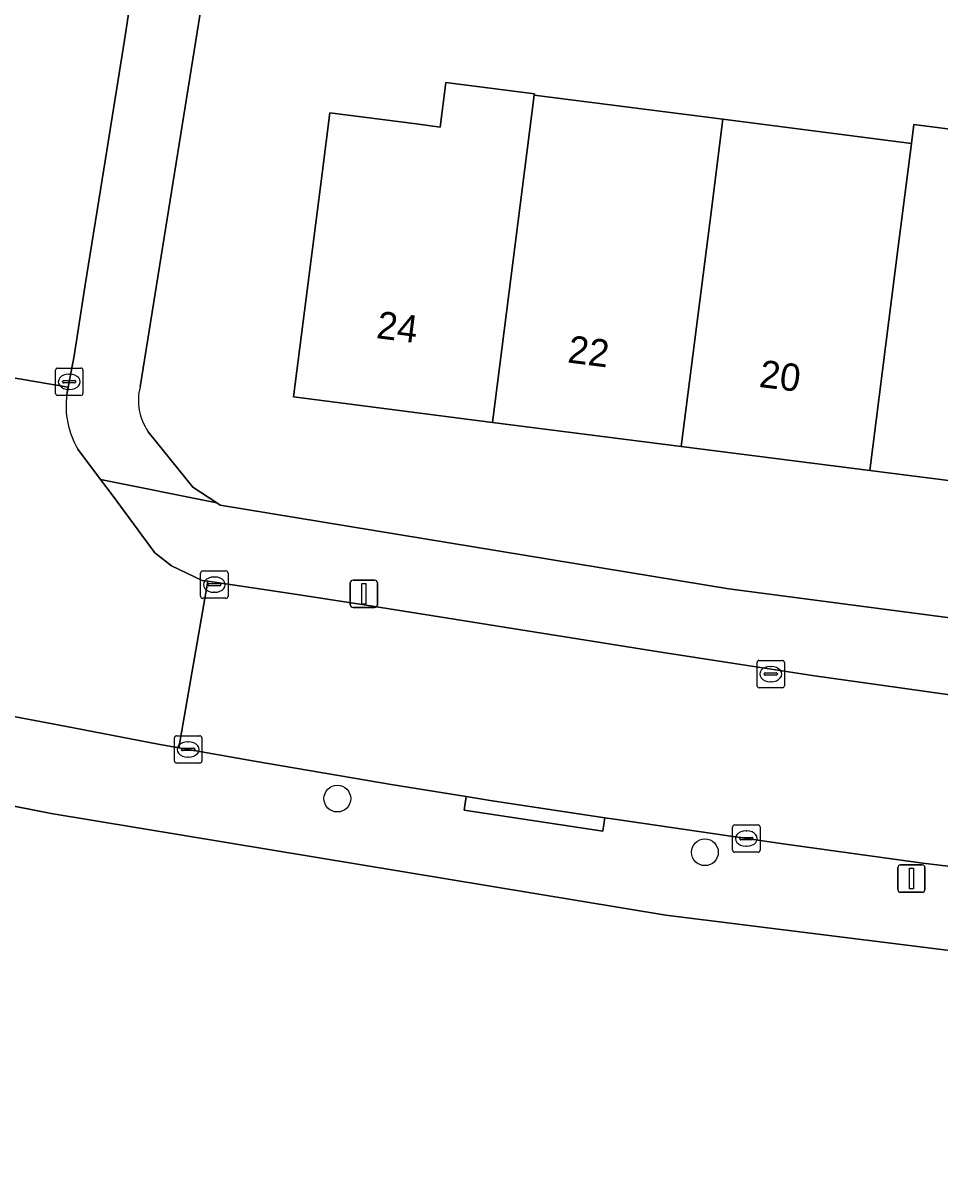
# Model space of a CAD drawing. Extents: x 161483 to 162250, y 379484 to 380833.
# Drawn here: x 162077.93 to 162111.46, y 380351.71 to 380393.94 of the extents above; entities that cross this region are included whole.
import ezdxf

# ---------------------------------------------------------------- set-up
doc = ezdxf.new("R2010")
doc.units = 0
for name, color, linetype in [('IMGEO_Boom', 7, 'Continuous'), ('IMGEO_Erf', 7, 'Continuous'), ('IMGEO_Kolk', 7, 'Continuous'), ('IMGEO_Lichtmast', 7, 'Continuous'), ('IMGEO_Pand', 7, 'Continuous'), ('IMGEO_Pand_nummerreeks', 7, 'Continuous'), ('IMGEO_Rijbaan_lokaal_open', 7, 'Continuous'), ('IMGEO_Voetpad_open', 7, 'Continuous')]:
    doc.layers.add(name, color=color, linetype=linetype)

msp = doc.modelspace()

# ---------------------------------------------------------------- linework, layer by layer
at = {"layer": 'IMGEO_Boom'}
for centre in [(162089.422, 380365.582), (162102.865, 380363.62)]:
    msp.add_circle(centre, 0.489, dxfattribs=at)
at = {"layer": 'IMGEO_Erf'}
for points in [[(162078.957, 380365.04), (162051.567, 380370.414), (162025.006, 380376.148), (162000, 380382.025), (161995.099, 380383.252), (161959.315, 380392.214), (161910.21, 380403.651), (161910.18, 380403.657), (161870.617, 380411.917), (161833.133, 380419.277), (161827.383, 380420.325), (161803.575, 380424.662), (161764.511, 380431.266), (161690.732, 380442.772), (161684.352, 380443.733), (161658.891, 380447.568)], [(162086.492, 380407.268), (162082.207, 380380.638)], [(162115.809, 380376.697), (162108.891, 380377.58), (162101.997, 380378.46), (162095.094, 380379.341), (162087.822, 380380.269), (162088.866, 380388.446), (162089.148, 380390.655), (162092.303, 380390.253), (162093.187, 380390.14), (162093.394, 380391.768), (162096.627, 380391.356), (162096.62, 380391.303), (162103.523, 380390.422), (162110.418, 380389.541), (162110.506, 380390.228), (162117.424, 380389.345)], [(162082.499, 380378.998), (162084.136, 380376.973), (162085.015, 380376.395), (162085.141, 380376.312), (162103.742, 380373.249), (162125.213, 380370.44), (162141.965, 380368.926), (162146.143, 380368.68)], [(162073.613, 380271.927), (162081.473, 380270.675), (162095.106, 380268.505), (162100.735, 380267.65), (162124.864, 380263.983), (162136.166, 380262.266), (162158.415, 380258.71), (162169.164, 380257.141), (162169.78, 380257.051), (162183.403, 380255.226), (162185.545, 380261.095), (162190.445, 380275.834), (162192.139, 380280.435), (162198.701, 380353.085), (162194.98, 380353.343), (162177.85, 380354.254), (162167.435, 380355.075), (162143.228, 380356.612), (162124.747, 380358.414), (162101.438, 380361.321), (162078.957, 380365.04)]]:
    msp.add_lwpolyline(points, dxfattribs=at)
msp.add_arc((162084.221, 380380.151), 2.072, 166.3942, 213.7971, dxfattribs=at)
at = {"layer": 'IMGEO_Kolk'}
for p, q in [((162079.118, 380380.4), (162079.118, 380381.252)), ((162079.193, 380381.326), (162080.045, 380381.326)), ((162079.606, 380381.106), (162079.631, 380381.106)), ((162080.119, 380381.252), (162080.119, 380380.4)), ((162079.377, 380380.82), (162079.377, 380380.832)), ((162079.815, 380380.783), (162079.417, 380380.783)), ((162079.42, 380380.869), (162079.818, 380380.869)), ((162079.861, 380380.832), (162079.861, 380380.82)), ((162080.045, 380380.326), (162079.193, 380380.326)), ((162079.629, 380380.546), (162079.604, 380380.546)), ((162084.498, 380373.906), (162085.35, 380373.906)), ((162084.423, 380372.98), (162084.423, 380373.832)), ((162084.911, 380373.686), (162084.936, 380373.686)), ((162085.424, 380373.832), (162085.424, 380372.98)), ((162084.682, 380373.4), (162084.682, 380373.412)), ((162085.12, 380373.363), (162084.722, 380373.363)), ((162084.725, 380373.449), (162085.123, 380373.449)), ((162084.934, 380373.126), (162084.909, 380373.126)), ((162085.166, 380373.412), (162085.166, 380373.4)), ((162085.35, 380372.906), (162084.498, 380372.906)), ((162104.772, 380369.71), (162104.772, 380370.562)), ((162104.847, 380370.636), (162105.699, 380370.636)), ((162105.773, 380370.562), (162105.773, 380369.71)), ((162105.031, 380370.13), (162105.031, 380370.142)), ((162105.074, 380370.179), (162105.472, 380370.179)), ((162105.26, 380370.416), (162105.285, 380370.416)), ((162105.515, 380370.142), (162105.515, 380370.13)), ((162105.469, 380370.093), (162105.071, 380370.093)), ((162105.283, 380369.856), (162105.258, 380369.856)), ((162105.699, 380369.636), (162104.847, 380369.636)), ((162083.466, 380366.954), (162083.466, 380367.806)), ((162083.541, 380367.88), (162084.393, 380367.88)), ((162083.954, 380367.66), (162083.979, 380367.66)), ((162084.467, 380367.806), (162084.467, 380366.954)), ((162083.725, 380367.374), (162083.725, 380367.386)), ((162084.163, 380367.337), (162083.765, 380367.337)), ((162083.768, 380367.423), (162084.166, 380367.423)), ((162084.209, 380367.386), (162084.209, 380367.374)), ((162084.393, 380366.88), (162083.541, 380366.88)), ((162083.977, 380367.1), (162083.952, 380367.1)), ((162103.955, 380364.621), (162104.807, 380364.621)), ((162103.88, 380363.695), (162103.88, 380364.547)), ((162104.368, 380364.401), (162104.393, 380364.401)), ((162104.881, 380364.547), (162104.881, 380363.695)), ((162104.139, 380364.115), (162104.139, 380364.127)), ((162104.577, 380364.078), (162104.179, 380364.078)), ((162104.182, 380364.164), (162104.58, 380364.164)), ((162104.391, 380363.841), (162104.366, 380363.841)), ((162104.623, 380364.127), (162104.623, 380364.115)), ((162104.807, 380363.621), (162103.955, 380363.621))]:
    msp.add_line(p, q, dxfattribs=at)
for points in [[(162079.118, 380380.4), (162079.118, 380381.252)], [(162079.193, 380381.326), (162080.045, 380381.326)], [(162080.119, 380381.252), (162080.119, 380380.4)], [(162080.045, 380380.326), (162079.193, 380380.326)], [(162084.498, 380373.906), (162085.35, 380373.906)], [(162084.423, 380372.98), (162084.423, 380373.832)], [(162085.424, 380373.832), (162085.424, 380372.98)], [(162085.35, 380372.906), (162084.498, 380372.906)], [(162104.772, 380369.71), (162104.772, 380370.562)], [(162104.847, 380370.636), (162105.699, 380370.636)], [(162105.773, 380370.562), (162105.773, 380369.71)], [(162105.699, 380369.636), (162104.847, 380369.636)], [(162083.466, 380366.954), (162083.466, 380367.806)], [(162083.541, 380367.88), (162084.393, 380367.88)], [(162084.467, 380367.806), (162084.467, 380366.954)], [(162084.393, 380366.88), (162083.541, 380366.88)], [(162103.955, 380364.621), (162104.807, 380364.621)], [(162103.88, 380363.695), (162103.88, 380364.547)], [(162104.881, 380364.547), (162104.881, 380363.695)], [(162104.807, 380363.621), (162103.955, 380363.621)]]:
    msp.add_lwpolyline(points, dxfattribs=at)
for centre, radius, start, end in [((162079.195, 380381.25), 0.0765, 91.552, 178.448), ((162079.195, 380381.25), 0.0765, 91.552, 178.448), ((162080.043, 380381.25), 0.0765, 1.552, 88.448), ((162080.043, 380381.25), 0.0765, 1.552, 88.448), ((162079.417, 380380.829), 0.0403, 85.8775, 175.7526), ((162079.414, 380380.819), 0.0366, 178.938, 274.7102), ((162079.818, 380380.826), 0.043, 264.8664, 352.4533), ((162079.822, 380380.831), 0.0386, 1.7309, 96.639), ((162079.195, 380380.402), 0.0765, 181.552, 268.448), ((162079.195, 380380.402), 0.0765, 181.552, 268.448), ((162080.043, 380380.402), 0.0765, 271.552, 358.448), ((162080.043, 380380.402), 0.0765, 271.552, 358.448), ((162084.5, 380373.83), 0.0765, 91.552, 178.448), ((162084.5, 380373.83), 0.0765, 91.552, 178.448), ((162085.348, 380373.83), 0.0765, 1.552, 88.448), ((162085.348, 380373.83), 0.0765, 1.552, 88.448), ((162084.722, 380373.409), 0.0403, 85.8775, 175.7526), ((162084.719, 380373.399), 0.0366, 178.938, 274.7102), ((162085.123, 380373.406), 0.043, 264.8664, 352.4533), ((162085.127, 380373.411), 0.0386, 1.7309, 96.639), ((162084.5, 380372.982), 0.0765, 181.552, 268.448), ((162084.5, 380372.982), 0.0765, 181.552, 268.448), ((162085.348, 380372.982), 0.0765, 271.552, 358.448), ((162085.348, 380372.982), 0.0765, 271.552, 358.448), ((162104.849, 380370.56), 0.0765, 91.552, 178.448), ((162104.849, 380370.56), 0.0765, 91.552, 178.448), ((162105.697, 380370.56), 0.0765, 1.552, 88.448), ((162105.697, 380370.56), 0.0765, 1.552, 88.448), ((162105.071, 380370.139), 0.0403, 85.8775, 175.7526), ((162105.068, 380370.129), 0.0366, 178.938, 274.7102), ((162105.472, 380370.136), 0.043, 264.8664, 352.4533), ((162105.476, 380370.141), 0.0386, 1.7309, 96.639), ((162104.849, 380369.712), 0.0765, 181.552, 268.448), ((162104.849, 380369.712), 0.0765, 181.552, 268.448), ((162105.697, 380369.712), 0.0765, 271.552, 358.448), ((162105.697, 380369.712), 0.0765, 271.552, 358.448), ((162083.543, 380367.804), 0.0765, 91.552, 178.448), ((162083.543, 380367.804), 0.0765, 91.552, 178.448), ((162084.391, 380367.804), 0.0765, 1.552, 88.448), ((162084.391, 380367.804), 0.0765, 1.552, 88.448), ((162083.765, 380367.383), 0.0403, 85.8775, 175.7526), ((162083.762, 380367.373), 0.0366, 178.938, 274.7102), ((162084.166, 380367.38), 0.043, 264.8664, 352.4533), ((162084.17, 380367.385), 0.0386, 1.7309, 96.639), ((162083.543, 380366.956), 0.0765, 181.552, 268.448), ((162083.543, 380366.956), 0.0765, 181.552, 268.448), ((162084.391, 380366.956), 0.0765, 271.552, 358.448), ((162084.391, 380366.956), 0.0765, 271.552, 358.448), ((162103.957, 380364.545), 0.0765, 91.552, 178.448), ((162103.957, 380364.545), 0.0765, 91.552, 178.448), ((162104.805, 380364.545), 0.0765, 1.552, 88.448), ((162104.805, 380364.545), 0.0765, 1.552, 88.448), ((162104.179, 380364.124), 0.0403, 85.8775, 175.7526), ((162104.176, 380364.114), 0.0366, 178.938, 274.7102), ((162104.58, 380364.121), 0.043, 264.8664, 352.4533), ((162104.584, 380364.126), 0.0386, 1.7309, 96.639), ((162103.957, 380363.697), 0.0765, 181.552, 268.448), ((162103.957, 380363.697), 0.0765, 181.552, 268.448), ((162104.805, 380363.697), 0.0765, 271.552, 358.448), ((162104.805, 380363.697), 0.0765, 271.552, 358.448)]:
    msp.add_arc(centre, radius, start, end, dxfattribs=at)
for centre, major_axis, ratio, start_param, end_param in [((162079.605, 380380.826), (-0.387, 0.002), 0.722429, 4.712389, 7.853982), ((162079.63, 380380.826), (-0.39, 0.002), 0.717154, 1.570796, 4.712389), ((162084.91, 380373.406), (-0.387, 0.002), 0.722429, 4.712389, 7.853982), ((162084.935, 380373.406), (-0.39, 0.002), 0.717154, 1.570796, 4.712389), ((162105.259, 380370.136), (-0.387, 0.002), 0.722429, 4.712389, 7.853982), ((162105.284, 380370.136), (-0.39, 0.002), 0.717154, 1.570796, 4.712389), ((162083.953, 380367.38), (-0.387, 0.002), 0.722429, 4.712389, 7.853982), ((162083.978, 380367.38), (-0.39, 0.002), 0.717154, 1.570796, 4.712389), ((162104.367, 380364.121), (-0.387, 0.002), 0.722429, 4.712389, 7.853982), ((162104.392, 380364.121), (-0.39, 0.002), 0.717154, 1.570796, 4.712389)]:
    msp.add_ellipse(centre, major_axis=major_axis, ratio=ratio, start_param=start_param, end_param=end_param, dxfattribs=at)
at = {"layer": 'IMGEO_Lichtmast'}
for p, q in [((162089.997, 380373.57), (162090.787, 380373.57)), ((162090.787, 380373.57), (162089.997, 380373.57)), ((162089.897, 380372.67), (162089.897, 380373.47)), ((162089.897, 380373.47), (162089.897, 380372.67)), ((162090.887, 380373.47), (162090.887, 380372.67)), ((162090.887, 380372.67), (162090.887, 380373.47)), ((162090.787, 380372.57), (162089.997, 380372.57)), ((162089.997, 380372.57), (162090.787, 380372.57)), ((162109.922, 380362.259), (162109.922, 380363.059)), ((162109.922, 380363.059), (162109.922, 380362.259)), ((162110.022, 380363.159), (162110.812, 380363.159)), ((162110.812, 380363.159), (162110.022, 380363.159)), ((162110.912, 380363.059), (162110.912, 380362.259)), ((162110.912, 380362.259), (162110.912, 380363.059)), ((162110.812, 380362.159), (162110.022, 380362.159)), ((162110.022, 380362.159), (162110.812, 380362.159))]:
    msp.add_line(p, q, dxfattribs=at)
for points in [[(162090.317, 380373.445), (162090.467, 380373.445), (162090.467, 380372.695), (162090.317, 380372.695), (162090.317, 380373.445)], [(162110.342, 380363.034), (162110.492, 380363.034), (162110.492, 380362.284), (162110.342, 380362.284), (162110.342, 380363.034)]]:
    msp.add_lwpolyline(points, dxfattribs=at)
for centre, start, end in [((162089.997, 380373.47), 90, 180), ((162089.997, 380373.47), 90, 180), ((162090.787, 380373.47), 0, 90), ((162090.787, 380373.47), 360, 90), ((162089.997, 380372.67), 180, 270), ((162089.997, 380372.67), 180, 270), ((162090.787, 380372.67), 270, 0), ((162090.787, 380372.67), 270, 0), ((162110.022, 380363.059), 90, 180), ((162110.022, 380363.059), 90, 180), ((162110.812, 380363.059), 0, 90), ((162110.812, 380363.059), 360, 90), ((162110.022, 380362.259), 180, 270), ((162110.022, 380362.259), 180, 270), ((162110.812, 380362.259), 270, 0), ((162110.812, 380362.259), 270, 0)]:
    msp.add_arc(centre, 0.1, start, end, dxfattribs=at)
at = {"layer": 'IMGEO_Pand'}
for points in [[(162096.62, 380391.303), (162096.627, 380391.356), (162093.394, 380391.768), (162093.187, 380390.14), (162092.303, 380390.253), (162089.148, 380390.655), (162088.866, 380388.446), (162087.822, 380380.269), (162095.094, 380379.341)], [(162103.523, 380390.422), (162096.62, 380391.303), (162095.094, 380379.341), (162101.997, 380378.46), (162103.04, 380386.637)], [(162103.523, 380390.422), (162103.04, 380386.637), (162101.997, 380378.46), (162108.891, 380377.58), (162109.935, 380385.757), (162110.418, 380389.541)], [(162117.36, 380388.847), (162117.372, 380388.942), (162117.424, 380389.345), (162110.506, 380390.228), (162110.418, 380389.541), (162109.935, 380385.757), (162108.891, 380377.58), (162115.809, 380376.697)]]:
    msp.add_lwpolyline(points, close=True, dxfattribs=at)
at = {"layer": 'IMGEO_Rijbaan_lokaal_open'}
for points in [[(162077.34, 380396.967), (162076.646, 380392.468), (162075.971, 380388.219), (162075.628, 380385.97), (162075.199, 380383.16), (162074.906, 380381.422), (162079.58, 380380.633), (162079.798, 380381.775), (162080.204, 380384.364), (162080.948, 380388.983), (162081.642, 380393.312), (162082.217, 380397.071)], [(162079.529, 380380.365), (162079.58, 380380.633), (162074.906, 380381.422), (162074.573, 380379.45)], [(162056.369, 380378.897), (162055.046, 380373.026), (162060.14, 380371.971), (162066.448, 380370.697), (162070.637, 380369.921), (162075.065, 380369.065), (162079.523, 380368.219), (162082.872, 380367.572), (162083.626, 380367.44), (162084.692, 380373.529), (162084.48, 380373.56), (162083.358, 380374.094), (162082.753, 380374.564), (162081.183, 380376.687)], [(162081.183, 380376.687), (162080.755, 380377.257), (162079.931, 380378.355)], [(162111.911, 380369.363), (162109.226, 380369.737), (162106.877, 380370.077), (162103.864, 380370.532), (162101.186, 380370.95), (162098.509, 380371.375), (162095.832, 380371.804), (162093.155, 380372.232), (162090.476, 380372.654), (162087.795, 380373.067), (162084.692, 380373.529), (162083.626, 380367.44), (162086.391, 380366.956), (162091.459, 380366.09), (162094.131, 380365.657), (162095.017, 380365.514), (162099.21, 380364.881), (162099.555, 380364.829), (162105.723, 380363.925), (162110.831, 380363.22), (162115.998, 380362.594)]]:
    msp.add_lwpolyline(points, dxfattribs=at)
msp.add_arc((162082.69, 380379.952), 3.188, 172.556, 210.0639, dxfattribs=at)
at = {"layer": 'IMGEO_Voetpad_open'}
for points in [[(162086.492, 380407.268), (162084.073, 380408.581), (162082.696, 380399.583), (162082.217, 380397.071), (162081.642, 380393.312), (162080.948, 380388.983), (162080.204, 380384.364), (162079.798, 380381.775), (162079.58, 380380.633), (162079.529, 380380.365)], [(162082.207, 380380.638), (162086.492, 380407.268)], [(161910.21, 380403.651), (161959.315, 380392.214), (161995.099, 380383.252), (162000, 380382.025), (162025.006, 380376.148), (162051.567, 380370.414), (162078.957, 380365.04), (162101.438, 380361.321), (162124.747, 380358.414), (162143.228, 380356.612), (162167.435, 380355.075), (162177.85, 380354.254), (162194.98, 380353.343), (162198.701, 380353.085), (162204.142, 380352.708), (162204.216, 380353.696)], [(162079.931, 380378.355), (162080.755, 380377.257), (162085.015, 380376.395), (162084.136, 380376.973), (162082.499, 380378.998)], [(162103.742, 380373.249), (162085.141, 380376.312), (162085.015, 380376.395), (162080.755, 380377.257), (162081.183, 380376.687), (162082.753, 380374.564), (162083.358, 380374.094), (162084.48, 380373.56), (162084.692, 380373.529), (162087.795, 380373.067), (162090.476, 380372.654), (162093.155, 380372.232), (162095.832, 380371.804), (162098.509, 380371.375), (162101.186, 380370.95), (162103.864, 380370.532), (162106.877, 380370.077), (162109.226, 380369.737), (162111.911, 380369.363)], [(162146.143, 380368.68), (162141.965, 380368.926), (162125.213, 380370.44), (162103.742, 380373.249)], [(162115.998, 380362.594), (162110.831, 380363.22), (162105.723, 380363.925), (162099.555, 380364.829), (162099.21, 380364.881), (162099.135, 380364.387), (162094.056, 380365.164), (162094.131, 380365.657), (162091.459, 380366.09), (162086.391, 380366.956), (162083.626, 380367.44), (162082.872, 380367.572), (162079.523, 380368.219), (162075.065, 380369.065)]]:
    msp.add_lwpolyline(points, dxfattribs=at)
msp.add_lwpolyline([(162099.21, 380364.881), (162095.017, 380365.514), (162094.131, 380365.657), (162094.056, 380365.164), (162099.135, 380364.387)], close=True, dxfattribs=at)
for centre, radius, start, end in [((162082.69, 380379.952), 3.188, 172.556, 210.0639), ((162084.221, 380380.151), 2.072, 166.3942, 213.7971)]:
    msp.add_arc(centre, radius, start, end, dxfattribs=at)

# ---------------------------------------------------------------- texts
at = {"layer": 'IMGEO_Pand_nummerreeks'}
for s, rotation, p in [('24', 352.7292, (162090.82, 380382.426)), ('22', 352.7274, (162097.815, 380381.535)), ('20', 352.7274, (162104.818, 380380.641))]:
    msp.add_text(s, height=1, rotation=rotation, dxfattribs=at).set_placement(p)

doc.saveas('drawing.dxf')
